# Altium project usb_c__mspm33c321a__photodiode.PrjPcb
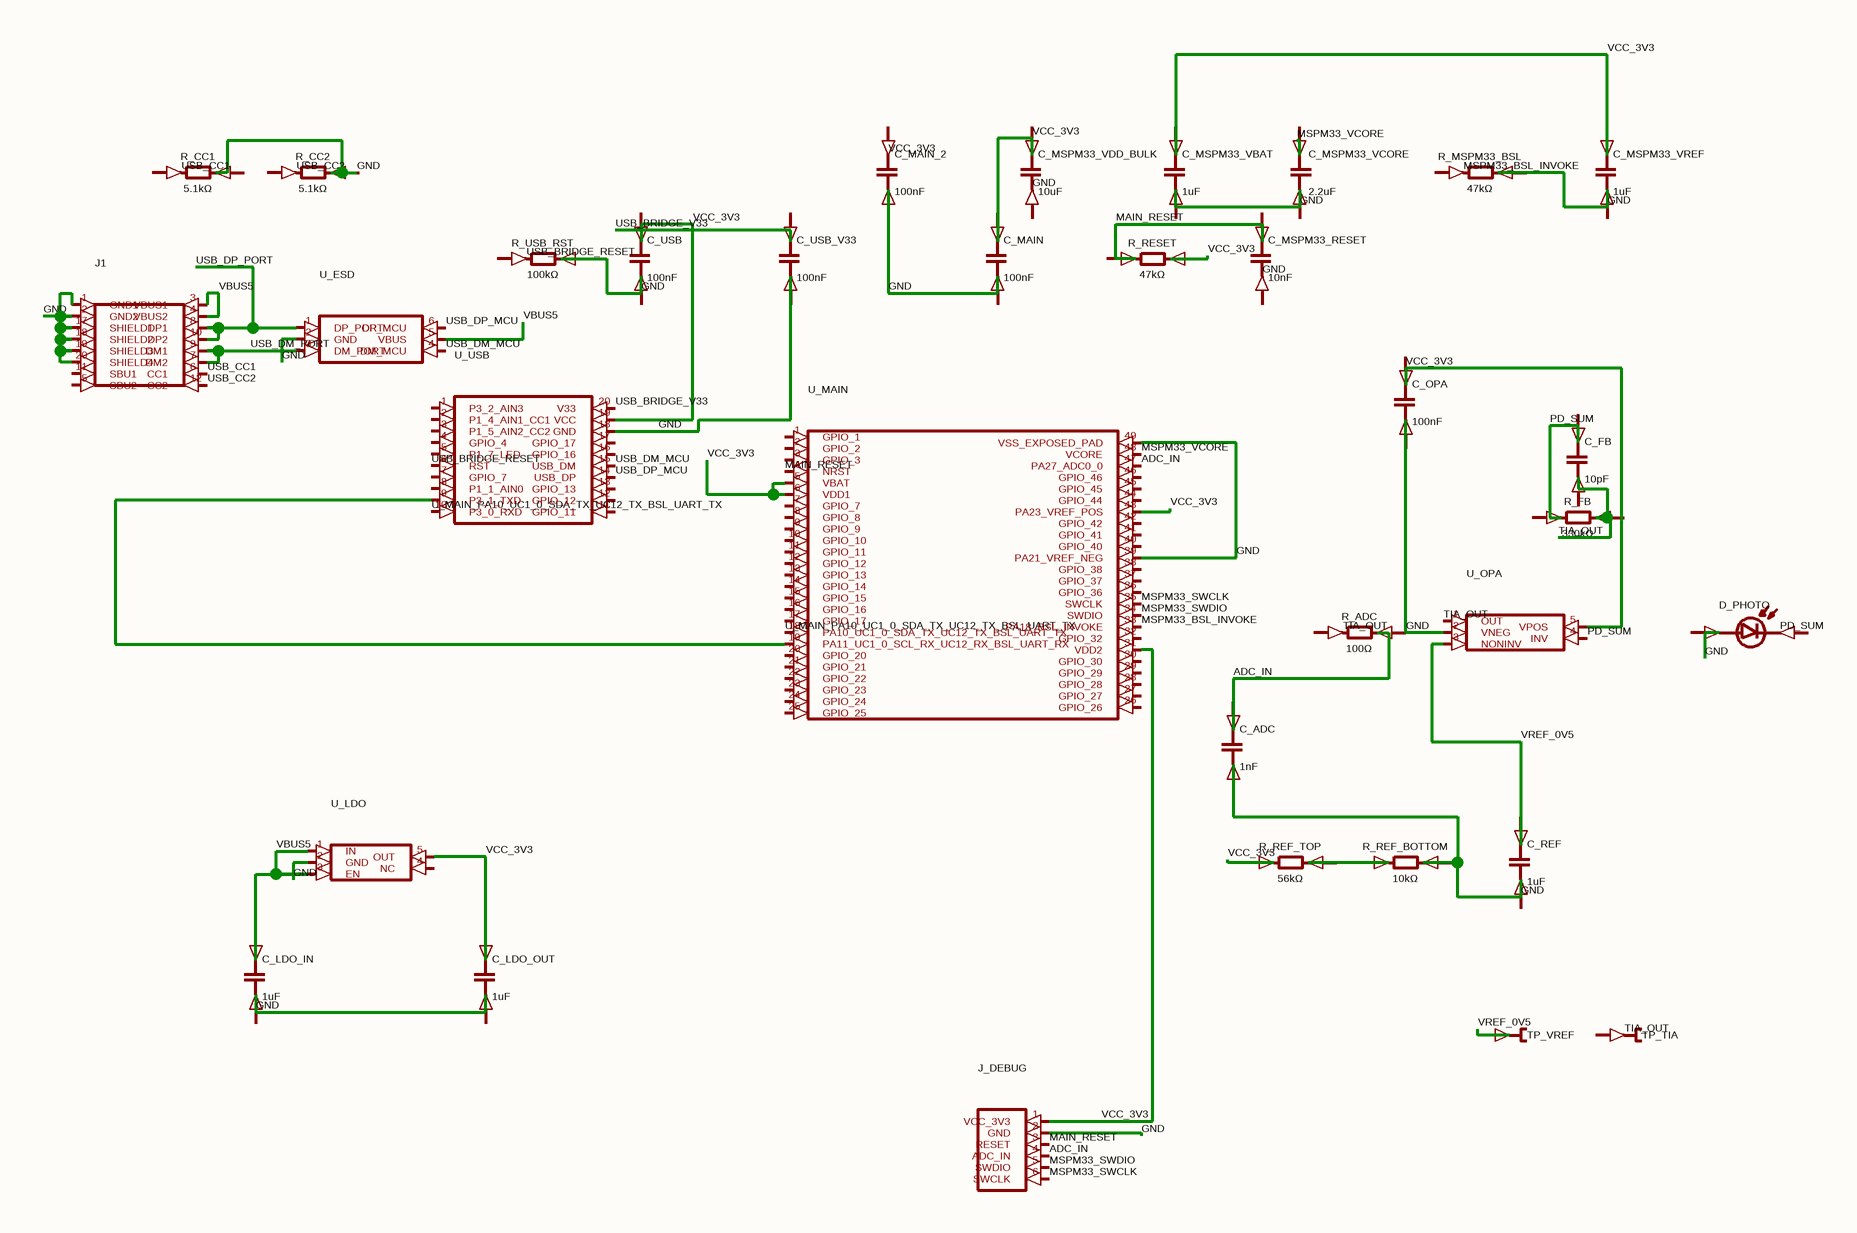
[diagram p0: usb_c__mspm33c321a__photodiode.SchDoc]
1 sheet, 34 parts. Net scope: global (net labels, ports and power ports of the same name join across sheets).
Board file: usb_c__mspm33c321a__photodiode.PcbDoc

## Sheet usb_c__mspm33c321a__photodiode.SchDoc
size 206 x 150 mm

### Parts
C_ADC  1nF
C_FB  10pF
C_LDO_IN  1uF
C_LDO_OUT  1uF
C_MAIN  100nF
C_MAIN_2  100nF
C_MSPM33_RESET  10nF
C_MSPM33_VBAT  1uF
C_MSPM33_VCORE  2.2uF
C_MSPM33_VDD_BULK  10uF
C_MSPM33_VREF  1uF
C_OPA  100nF
C_REF  1uF
C_USB  100nF
C_USB_V33  100nF
D_PHOTO  (no value)
J1  (no value)
J_DEBUG  (no value)
R_ADC  100Ω
R_CC1  5.1kΩ
R_CC2  5.1kΩ
R_FB  330kΩ
R_MSPM33_BSL  47kΩ
R_REF_BOTTOM  10kΩ
R_REF_TOP  56kΩ
R_RESET  47kΩ
R_USB_RST  100kΩ
TP_TIA  (no value)
TP_VREF  (no value)
U_ESD  (no value)
U_LDO  (no value)
U_MAIN  (no value)
U_OPA  (no value)
U_USB  (no value)

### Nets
ADC_IN: C_ADC.1(anode) J_DEBUG.4(ADC_IN) U_MAIN.47(PA27_ADC0_0)
GND: C_ADC.2(cathode) C_LDO_IN.1(anode) C_MAIN_2.2(cathode) C_OPA.2(cathode) C_USB_V33.2(cathode) J1.1(GND1) J1.2(GND2) J1.3(VBUS1) J1.4(VBUS2) J1.7(DM2) J1.9(DM1) J1.17(SHIELD1) J1.18(SHIELD2) J1.19(SHIELD3) J1.20(SHIELD4) J_DEBUG.2(GND) R_ADC.2(cathode) R_MSPM33_BSL.2(cathode) R_REF_BOTTOM.2(cathode) R_USB_RST.2(cathode) U_ESD.2(GND) U_ESD.3(DM_PORT) U_ESD.5(VBUS) U_LDO.1(IN) U_LDO.2(GND) U_LDO.3(EN) U_MAIN.39(PA21_VREF_NEG) U_MAIN.49(VSS_EXPOSED_PAD) U_OPA.2(VNEG) U_USB.18(GND)  [also labelled USB_DM_PORT, VBUS5]
MAIN_RESET: J_DEBUG.3(RESET) U_MAIN.4(NRST)
MSPM33_BSL_INVOKE: U_MAIN.33(PA18_BSL_INVOKE)
MSPM33_SWCLK: J_DEBUG.6(SWCLK) U_MAIN.35(SWCLK)
MSPM33_SWDIO: J_DEBUG.5(SWDIO) U_MAIN.34(SWDIO)
MSPM33_VCORE: U_MAIN.48(VCORE)
PD_SUM: U_OPA.4(INV)
TIA_OUT: U_OPA.1(OUT)
U_MAIN_PA10_UC1_0_SDA_TX_UC12_TX_BSL_UART_TX: U_MAIN.18(PA10_UC1_0_SDA_TX_UC12_TX_BSL_UART_TX) U_USB.10(P3_0_RXD)
USB_BRIDGE_RESET: U_USB.6(RST)
USB_BRIDGE_V33: C_LDO_OUT.1(anode) C_MAIN.1(anode) C_MSPM33_VBAT.1(anode) C_MSPM33_VREF.1(anode) J_DEBUG.1(VCC_3V3) R_REF_TOP.1(anode) R_RESET.2(cathode) U_LDO.5(OUT) U_MAIN.5(VBAT) U_MAIN.6(VDD1) U_MAIN.31(VDD2) U_MAIN.43(PA23_VREF_POS) U_OPA.5(VPOS) U_USB.19(VCC) U_USB.20(V33)  [also labelled VCC_3V3]
USB_CC1: J1.6(CC1)
USB_CC2: J1.12(CC2)
USB_DM_MCU: U_ESD.4(DM_MCU) U_USB.15(USB_DM)
USB_DP_MCU: U_ESD.6(DP_MCU) U_USB.14(USB_DP)
USB_DP_PORT: J1.8(DP1) J1.10(DP2) U_ESD.1(DP_PORT)
VREF_0V5: C_REF.1(anode) TP_VREF.1(pin1) U_OPA.3(NONINV)
NetR_REF_BOTTOM_1: R_REF_BOTTOM.1(anode) R_REF_TOP.2(cathode)
NetU_MAIN_19: U_MAIN.19(PA11_UC1_0_SCL_RX_UC12_RX_BSL_UART_RX) U_USB.9(P3_1_TXD)

Not connected (* = marked no-connect by the designer): C_FB 1(anode) 2(cathode); C_LDO_IN 2(cathode); C_LDO_OUT 2(cathode); C_MAIN 2(cathode); C_MAIN_2 1(anode); C_MSPM33_RESET 1(anode) 2(cathode); C_MSPM33_VBAT 2(cathode); C_MSPM33_VCORE 1(anode) 2(cathode); C_MSPM33_VDD_BULK 1(anode) 2(cathode); C_MSPM33_VREF 2(cathode); C_OPA 1(anode); C_REF 2(cathode); C_USB 1(anode) 2(cathode); C_USB_V33 1(anode); D_PHOTO 1(anode) 2(cathode); J1 5(SBU2) 11(SBU1); R_ADC 1(anode); R_CC1 1(anode) 2(cathode); R_CC2 1(anode) 2(cathode); R_FB 1(anode) 2(cathode); R_MSPM33_BSL 1(anode); R_RESET 1(anode); R_USB_RST 1(anode); TP_TIA 1(pin1); U_LDO 4(NC); U_MAIN 1(GPIO_1) 2(GPIO_2) 3(GPIO_3) 7(GPIO_7) 8(GPIO_8) 9(GPIO_9) 10(GPIO_10) 11(GPIO_11) 12(GPIO_12) 13(GPIO_13) 14(GPIO_14) 15(GPIO_15) 16(GPIO_16) 17(GPIO_17) 20(GPIO_20) 21(GPIO_21) 22(GPIO_22) 23(GPIO_23) 24(GPIO_24) 25(GPIO_25) 26(GPIO_26) 27(GPIO_27) 28(GPIO_28) 29(GPIO_29) 30(GPIO_30) 32(GPIO_32) 36(GPIO_36) 37(GPIO_37) 38(GPIO_38) 40(GPIO_40) 41(GPIO_41) 42(GPIO_42) 44(GPIO_44) 45(GPIO_45) 46(GPIO_46); U_USB 1(P3_2_AIN3) 2(P1_4_AIN1_CC1) 3(P1_5_AIN2_CC2) 4(GPIO_4) 5(P1_7_LED) 7(GPIO_7) 8(P1_1_AIN0) 11(GPIO_11) 12(GPIO_12) 13(GPIO_13) 16(GPIO_16) 17(GPIO_17)

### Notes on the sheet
- Labels drawn without touching a wire or pin: GND, MSPM33_BSL_INVOKE, PD_SUM, TIA_OUT, USB_BRIDGE_RESET, USB_CC1, USB_CC2, VCC_3V3

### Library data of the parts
C_ADC C_FB C_LDO_IN C_LDO_OUT C_MAIN C_MAIN_2 C_MSPM33_RESET C_MSPM33_VBAT C_MSPM33_VCORE C_MSPM33_VDD_BULK C_MSPM33_VREF C_OPA C_REF C_USB C_USB_V33 = capacitor_down
D_PHOTO = photodiode_horz
J1 = J1
J_DEBUG = J_DEBUG
R_ADC R_CC1 R_CC2 R_FB R_MSPM33_BSL R_REF_BOTTOM R_REF_TOP R_RESET R_USB_RST = boxresistor_right
TP_TIA TP_VREF = testpoint_right
U_ESD = U_ESD
U_LDO = U_LDO
U_MAIN = U_MAIN
U_OPA = U_OPA
U_USB = U_USB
